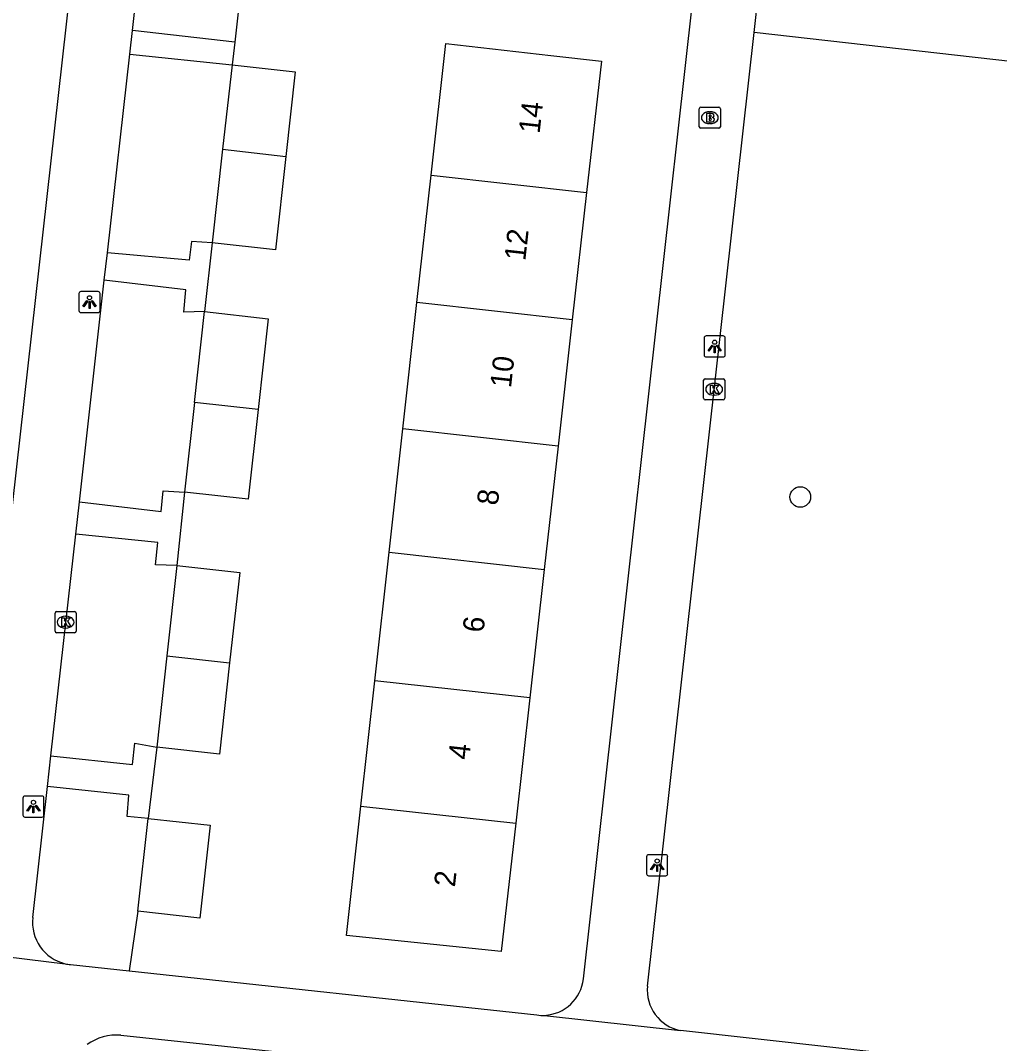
# Model space of a CAD drawing. Extents: x 161928 to 163055, y 386475 to 387428.
# Drawn here: x 162180.12 to 162226.46, y 387154.99 to 387203.42 of the extents above; entities that cross this region are included whole.
import ezdxf

# ---------------------------------------------------------------- set-up
doc = ezdxf.new("R2010")
doc.units = 0
for name, color, linetype in [('IMGEO_Boom', 7, 'Continuous'), ('IMGEO_Brandkraan', 7, 'Continuous'), ('IMGEO_Groenvoorziening', 7, 'Continuous'), ('IMGEO_Kolk', 7, 'Continuous'), ('IMGEO_Lichtpunt', 7, 'Continuous'), ('IMGEO_Pand', 7, 'Continuous'), ('IMGEO_Pand_nummerreeks', 7, 'Continuous'), ('IMGEO_Voetpad_open', 7, 'Continuous')]:
    doc.layers.add(name, color=color, linetype=linetype)

msp = doc.modelspace()

# ---------------------------------------------------------------- linework, layer by layer
at = {"layer": 'IMGEO_Boom'}
msp.add_circle((162217.03, 387180.861), 0.489, dxfattribs=at)
at = {"layer": 'IMGEO_Brandkraan'}
for p, q in [((162212.247, 387198.388), (162212.247, 387199.24)), ((162212.322, 387199.314), (162213.174, 387199.314)), ((162212.735, 387199.094), (162212.76, 387199.094)), ((162213.248, 387199.24), (162213.248, 387198.388)), ((162212.758, 387198.534), (162212.733, 387198.534)), ((162213.174, 387198.314), (162212.322, 387198.314))]:
    msp.add_line(p, q, dxfattribs=at)
for points in [[(162212.247, 387198.388), (162212.247, 387199.24)], [(162212.322, 387199.314), (162213.174, 387199.314)], [(162212.595, 387199.014), (162212.595, 387198.614), (162212.808, 387198.614)], [(162212.826, 387199.014), (162212.595, 387199.014)], [(162212.774, 387198.933), (162212.72, 387198.933), (162212.72, 387198.857)], [(162212.72, 387198.857), (162212.773, 387198.857)], [(162213.248, 387199.24), (162213.248, 387198.388)], [(162212.782, 387198.781), (162212.72, 387198.781), (162212.72, 387198.7)], [(162212.72, 387198.7), (162212.782, 387198.7)], [(162213.174, 387198.314), (162212.322, 387198.314)]]:
    msp.add_lwpolyline(points, dxfattribs=at)
for centre, radius, start, end in [((162212.324, 387199.238), 0.0765, 91.552, 178.448), ((162212.324, 387199.238), 0.0765, 91.552, 178.448), ((162212.775, 387198.895), 0.0379, 267.8285, 90.9355), ((162212.83, 387198.869), 0.145, 59.4692, 91.5367), ((162212.855, 387198.916), 0.0922, 285.5137, 58.1501), ((162213.172, 387199.238), 0.0765, 1.552, 88.448), ((162213.172, 387199.238), 0.0765, 1.552, 88.448), ((162212.324, 387198.39), 0.0765, 181.552, 268.448), ((162212.324, 387198.39), 0.0765, 181.552, 268.448), ((162212.783, 387198.74), 0.0404, 269.8759, 90.5077), ((162212.814, 387198.865), 0.251, 268.6676, 293.5347), ((162212.86, 387198.724), 0.105, 301.3115, 78.989), ((162213.172, 387198.39), 0.0765, 271.552, 358.448), ((162213.172, 387198.39), 0.0765, 271.552, 358.448)]:
    msp.add_arc(centre, radius, start, end, dxfattribs=at)
for centre, major_axis, ratio, start_param, end_param in [((162212.734, 387198.814), (-0.387, 0.002), 0.722429, 4.712389, 7.853982), ((162212.759, 387198.814), (-0.39, 0.002), 0.717154, 1.570796, 4.712389)]:
    msp.add_ellipse(centre, major_axis=major_axis, ratio=ratio, start_param=start_param, end_param=end_param, dxfattribs=at)
at = {"layer": 'IMGEO_Groenvoorziening'}
for points in [[(162190.742, 387206.64), (162190.27, 387202.387)], [(162248.683, 387157.87), (162231.107, 387159.904), (162235.766, 387200.474), (162214.845, 387202.842)], [(162185.672, 387161.254), (162185.261, 387158.428)]]:
    msp.add_lwpolyline(points, dxfattribs=at)
at = {"layer": 'IMGEO_Kolk'}
for p, q in [((162212.451, 387185.534), (162212.451, 387186.386)), ((162212.526, 387186.46), (162213.378, 387186.46)), ((162213.452, 387186.386), (162213.452, 387185.534)), ((162212.939, 387186.24), (162212.964, 387186.24)), ((162213.378, 387185.46), (162212.526, 387185.46)), ((162212.962, 387185.68), (162212.937, 387185.68)), ((162181.752, 387174.512), (162181.752, 387175.364)), ((162181.827, 387175.438), (162182.679, 387175.438)), ((162182.24, 387175.218), (162182.265, 387175.218)), ((162182.753, 387175.364), (162182.753, 387174.512)), ((162182.263, 387174.658), (162182.238, 387174.658)), ((162182.679, 387174.438), (162181.827, 387174.438))]:
    msp.add_line(p, q, dxfattribs=at)
for points in [[(162212.451, 387185.534), (162212.451, 387186.386)], [(162212.526, 387186.46), (162213.378, 387186.46)], [(162213.452, 387186.386), (162213.452, 387185.534)], [(162212.772, 387186.16), (162212.895, 387186.16), (162212.895, 387186.009), (162213.025, 387186.16), (162213.189, 387186.16), (162213.043, 387186.009), (162213.196, 387185.76), (162213.044, 387185.76), (162212.959, 387185.924), (162212.895, 387185.857), (162212.895, 387185.76), (162212.772, 387185.76), (162212.772, 387186.16)], [(162213.378, 387185.46), (162212.526, 387185.46)], [(162181.752, 387174.512), (162181.752, 387175.364)], [(162181.827, 387175.438), (162182.679, 387175.438)], [(162182.073, 387175.138), (162182.196, 387175.138), (162182.196, 387174.987), (162182.326, 387175.138), (162182.49, 387175.138), (162182.344, 387174.987), (162182.497, 387174.738), (162182.345, 387174.738), (162182.26, 387174.902), (162182.196, 387174.835), (162182.196, 387174.738), (162182.073, 387174.738), (162182.073, 387175.138)], [(162182.753, 387175.364), (162182.753, 387174.512)], [(162182.679, 387174.438), (162181.827, 387174.438)]]:
    msp.add_lwpolyline(points, dxfattribs=at)
for centre, start, end in [((162212.528, 387186.384), 91.552, 178.448), ((162212.528, 387186.384), 91.552, 178.448), ((162213.376, 387186.384), 1.552, 88.448), ((162213.376, 387186.384), 1.552, 88.448), ((162212.528, 387185.536), 181.552, 268.448), ((162212.528, 387185.536), 181.552, 268.448), ((162213.376, 387185.536), 271.552, 358.448), ((162213.376, 387185.536), 271.552, 358.448), ((162181.829, 387175.362), 91.552, 178.448), ((162181.829, 387175.362), 91.552, 178.448), ((162182.677, 387175.362), 1.552, 88.448), ((162182.677, 387175.362), 1.552, 88.448), ((162181.829, 387174.514), 181.552, 268.448), ((162181.829, 387174.514), 181.552, 268.448), ((162182.677, 387174.514), 271.552, 358.448), ((162182.677, 387174.514), 271.552, 358.448)]:
    msp.add_arc(centre, 0.0765, start, end, dxfattribs=at)
for centre, major_axis, ratio, start_param, end_param in [((162212.938, 387185.96), (-0.387, 0.002), 0.722429, 4.712389, 7.853982), ((162212.963, 387185.96), (-0.39, 0.002), 0.717154, 1.570796, 4.712389), ((162182.239, 387174.938), (-0.387, 0.002), 0.722429, 4.712389, 7.853982), ((162182.264, 387174.938), (-0.39, 0.002), 0.717154, 1.570796, 4.712389)]:
    msp.add_ellipse(centre, major_axis=major_axis, ratio=ratio, start_param=start_param, end_param=end_param, dxfattribs=at)
at = {"layer": 'IMGEO_Lichtpunt'}
for p, q in [((162182.885, 387190.492), (162182.885, 387189.685)), ((162182.885, 387190.492), (162182.885, 387189.685)), ((162183.787, 387190.587), (162182.979, 387190.587)), ((162183.787, 387190.587), (162182.979, 387190.587)), ((162183.881, 387189.685), (162183.881, 387190.492)), ((162183.881, 387189.685), (162183.881, 387190.492)), ((162182.979, 387189.591), (162183.787, 387189.591)), ((162182.979, 387189.591), (162183.787, 387189.591)), ((162212.478, 387188.389), (162212.478, 387187.582)), ((162212.478, 387188.389), (162212.478, 387187.582)), ((162213.38, 387188.484), (162212.572, 387188.484)), ((162213.38, 387188.484), (162212.572, 387188.484)), ((162213.474, 387187.582), (162213.474, 387188.389)), ((162213.474, 387187.582), (162213.474, 387188.389)), ((162212.572, 387187.488), (162213.38, 387187.488)), ((162212.572, 387187.488), (162213.38, 387187.488)), ((162180.233, 387166.613), (162180.233, 387165.806)), ((162180.233, 387166.613), (162180.233, 387165.806)), ((162181.135, 387166.708), (162180.327, 387166.708)), ((162181.135, 387166.708), (162180.327, 387166.708)), ((162181.229, 387165.806), (162181.229, 387166.613)), ((162181.229, 387165.806), (162181.229, 387166.613)), ((162180.327, 387165.712), (162181.135, 387165.712)), ((162180.327, 387165.712), (162181.135, 387165.712)), ((162209.755, 387163.835), (162209.755, 387163.028)), ((162209.755, 387163.835), (162209.755, 387163.028)), ((162210.657, 387163.93), (162209.849, 387163.93)), ((162210.657, 387163.93), (162209.849, 387163.93)), ((162210.751, 387163.028), (162210.751, 387163.835)), ((162210.751, 387163.028), (162210.751, 387163.835)), ((162209.849, 387162.934), (162210.657, 387162.934)), ((162209.849, 387162.934), (162210.657, 387162.934))]:
    msp.add_line(p, q, dxfattribs=at)
for points in [[(162183.259, 387190.156), (162183.298, 387190.128), (162183.11, 387189.866), (162183.072, 387189.893), (162183.259, 387190.156)], [(162183.471, 387190.128), (162183.509, 387190.155), (162183.696, 387189.893), (162183.657, 387189.865), (162183.471, 387190.128)], [(162183.361, 387190.108), (162183.408, 387190.108), (162183.408, 387189.786), (162183.361, 387189.786), (162183.361, 387190.108)], [(162212.852, 387188.053), (162212.891, 387188.025), (162212.703, 387187.763), (162212.665, 387187.79), (162212.852, 387188.053)], [(162212.954, 387188.005), (162213.001, 387188.005), (162213.001, 387187.683), (162212.954, 387187.683), (162212.954, 387188.005)], [(162213.064, 387188.025), (162213.102, 387188.052), (162213.289, 387187.79), (162213.25, 387187.762), (162213.064, 387188.025)], [(162180.607, 387166.277), (162180.646, 387166.249), (162180.458, 387165.987), (162180.42, 387166.014), (162180.607, 387166.277)], [(162180.709, 387166.229), (162180.756, 387166.229), (162180.756, 387165.907), (162180.709, 387165.907), (162180.709, 387166.229)], [(162180.819, 387166.249), (162180.857, 387166.276), (162181.044, 387166.014), (162181.005, 387165.986), (162180.819, 387166.249)], [(162210.129, 387163.499), (162210.168, 387163.471), (162209.98, 387163.209), (162209.942, 387163.236), (162210.129, 387163.499)], [(162210.341, 387163.471), (162210.379, 387163.498), (162210.566, 387163.236), (162210.527, 387163.208), (162210.341, 387163.471)], [(162210.231, 387163.451), (162210.278, 387163.451), (162210.278, 387163.129), (162210.231, 387163.129), (162210.231, 387163.451)]]:
    msp.add_lwpolyline(points, dxfattribs=at)
for centre in [(162183.384, 387190.29), (162212.977, 387188.187), (162180.732, 387166.411), (162210.254, 387163.633)]:
    msp.add_circle(centre, 0.0994, dxfattribs=at)
for centre, start, end in [((162182.979, 387190.492), 90, 180), ((162182.979, 387190.492), 90, 180), ((162183.787, 387190.492), 0, 90), ((162183.787, 387190.492), 0, 90), ((162182.979, 387189.685), 180, 270), ((162182.979, 387189.685), 180, 270), ((162183.787, 387189.685), 270, 0), ((162183.787, 387189.685), 270, 360), ((162212.572, 387188.389), 90, 180), ((162212.572, 387188.389), 90, 180), ((162213.38, 387188.389), 0, 90), ((162213.38, 387188.389), 0, 90), ((162212.572, 387187.582), 180, 270), ((162212.572, 387187.582), 180, 270), ((162213.38, 387187.582), 270, 0), ((162213.38, 387187.582), 270, 360), ((162180.327, 387166.613), 90, 180), ((162180.327, 387166.613), 90, 180), ((162181.135, 387166.613), 0, 90), ((162181.135, 387166.613), 0, 90), ((162180.327, 387165.806), 180, 270), ((162180.327, 387165.806), 180, 270), ((162181.135, 387165.806), 270, 0), ((162181.135, 387165.806), 270, 360), ((162209.849, 387163.835), 90, 180), ((162209.849, 387163.835), 90, 180), ((162210.657, 387163.835), 0, 90), ((162210.657, 387163.835), 0, 90), ((162209.849, 387163.028), 180, 270), ((162209.849, 387163.028), 180, 270), ((162210.657, 387163.028), 270, 0), ((162210.657, 387163.028), 270, 360)]:
    msp.add_arc(centre, 0.0946, start, end, dxfattribs=at)
at = {"layer": 'IMGEO_Pand'}
for points in [[(162199.55, 387196.094), (162200.243, 387202.321), (162205.228, 387201.761), (162207.612, 387201.493), (162206.913, 387195.275)], [(162190.129, 387201.318), (162189.684, 387197.319)], [(162190.129, 387201.318), (162193.12, 387200.986), (162192.675, 387196.983)], [(162189.684, 387197.319), (162189.192, 387192.889)], [(162192.675, 387196.983), (162192.183, 387192.557), (162189.192, 387192.889)], [(162189.684, 387197.319), (162192.675, 387196.983)], [(162198.879, 387190.061), (162199.55, 387196.094)], [(162199.55, 387196.094), (162206.913, 387195.275)], [(162206.913, 387195.275), (162206.235, 387189.243)], [(162198.215, 387184.089), (162198.879, 387190.061)], [(162206.235, 387189.243), (162198.879, 387190.061)], [(162188.351, 387185.335), (162188.829, 387189.633)], [(162188.829, 387189.633), (162191.841, 387189.298), (162191.362, 387184.997)], [(162206.235, 387189.243), (162205.563, 387183.271)], [(162188.351, 387185.335), (162187.879, 387181.088)], [(162191.362, 387184.997), (162188.351, 387185.335)], [(162191.362, 387184.997), (162190.89, 387180.753), (162187.879, 387181.088)], [(162197.564, 387178.244), (162198.215, 387184.089)], [(162205.563, 387183.271), (162198.215, 387184.089)], [(162205.563, 387183.271), (162204.906, 387177.427)], [(162196.888, 387172.165), (162197.564, 387178.244)], [(162197.564, 387178.244), (162204.906, 387177.427)], [(162187.522, 387177.616), (162187.047, 387173.347)], [(162187.522, 387177.616), (162190.493, 387177.286), (162190.018, 387173.013)], [(162204.906, 387177.427), (162204.223, 387171.349)], [(162187.047, 387173.347), (162186.566, 387169.019)], [(162187.047, 387173.347), (162190.018, 387173.013)], [(162190.018, 387173.013), (162189.537, 387168.688), (162186.566, 387169.019)], [(162196.228, 387166.235), (162196.888, 387172.165)], [(162204.223, 387171.349), (162196.888, 387172.165)], [(162204.223, 387171.349), (162203.557, 387165.42)], [(162203.557, 387165.42), (162202.875, 387159.357), (162195.546, 387160.102), (162196.228, 387166.235)], [(162196.228, 387166.235), (162203.557, 387165.42)], [(162186.161, 387165.651), (162189.098, 387165.325), (162188.609, 387160.928), (162185.672, 387161.254)], [(162185.672, 387161.254), (162186.161, 387165.651)]]:
    msp.add_lwpolyline(points, dxfattribs=at)
at = {"layer": 'IMGEO_Voetpad_open'}
for points in [[(162184.099, 387219.432), (162177.534, 387161.061)], [(162185.414, 387202.938), (162185.893, 387207.187)], [(162214.845, 387202.842), (162215.263, 387206.574), (162215.267, 387206.602)], [(162206.762, 387158.058), (162211.92, 387204.25)], [(162185.289, 387201.824), (162185.414, 387202.938)], [(162190.27, 387202.387), (162185.414, 387202.938)], [(162209.794, 387157.716), (162214.845, 387202.842)], [(162190.27, 387202.387), (162190.129, 387201.318)], [(162184.231, 387192.414), (162185.289, 387201.824)], [(162185.289, 387201.824), (162190.129, 387201.318)], [(162189.192, 387192.889), (162188.205, 387192.956), (162188.109, 387192.068), (162184.231, 387192.414)], [(162189.192, 387192.889), (162188.829, 387189.633)], [(162184.085, 387191.117), (162184.231, 387192.414)], [(162182.906, 387180.628), (162184.085, 387191.117)], [(162188.829, 387189.633), (162187.85, 387189.607), (162187.946, 387190.66), (162184.085, 387191.117)], [(162182.906, 387180.628), (162186.775, 387180.181), (162186.871, 387181.145), (162187.879, 387181.088)], [(162187.879, 387181.088), (162187.522, 387177.616)], [(162182.735, 387179.104), (162182.906, 387180.628)], [(162181.555, 387168.604), (162182.735, 387179.104)], [(162187.522, 387177.616), (162186.515, 387177.656), (162186.611, 387178.709), (162182.735, 387179.104)], [(162181.555, 387168.604), (162185.427, 387168.205), (162185.536, 387169.207), (162186.566, 387169.019)], [(162186.566, 387169.019), (162186.161, 387165.651)], [(162181.392, 387167.156), (162181.555, 387168.604)], [(162180.696, 387160.966), (162181.392, 387167.156)], [(162186.161, 387165.651), (162185.167, 387165.744), (162185.238, 387166.746), (162181.392, 387167.156)], [(162175.662, 387159.569), (162182.239, 387158.771)], [(162182.492, 387158.727), (162185.261, 387158.428)], [(162185.261, 387158.428), (162204.555, 387156.345)], [(162204.927, 387156.328), (162211.355, 387155.609)], [(162184.863, 387155.391), (162201.078, 387153.663)], [(162247.975, 387151.529), (162211.355, 387155.609)]]:
    msp.add_lwpolyline(points, dxfattribs=at)
for centre, radius, start, end in [((162182.709, 387160.741), 2.026, 173.6367, 256.5748), ((162182.716, 387160.764), 2.049, 256.5418, 263.7266), ((162204.826, 387158.273), 1.948, 272.9724, 353.6535), ((162211.733, 387157.521), 1.949, 174.2581, 258.8087), ((162204.834, 387158.372), 2.046, 262.1613, 272.6057), ((162184.694, 387152.928), 2.469, 86.0647, 125.0913)]:
    msp.add_arc(centre, radius, start, end, dxfattribs=at)

# ---------------------------------------------------------------- texts
at = {"layer": 'IMGEO_Pand_nummerreeks'}
for s, p in [('14', (162204.687, 387198.034)), ('12', (162204.01, 387192.012)), ('10', (162203.334, 387185.998)), ('8', (162202.709, 387180.437)), ('6', (162202.032, 387174.414)), ('4', (162201.355, 387168.394)), ('2', (162200.679, 387162.373))]:
    msp.add_text(s, height=1, rotation=83.5856, dxfattribs=at).set_placement(p)

doc.saveas('drawing.dxf')
